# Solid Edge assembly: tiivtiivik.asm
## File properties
Author: Argu
Template: Iso Assembly.asm
Last saved by: argo
Revision: 52
Application: Solid Edge
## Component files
rool.par
istuk.psm
istuk_mir.psm
rool_mir.par
motor.par
rotor.par
ratas.par
rotor_mir1.par
ratas_mir.par
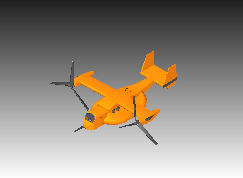
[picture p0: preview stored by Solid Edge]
